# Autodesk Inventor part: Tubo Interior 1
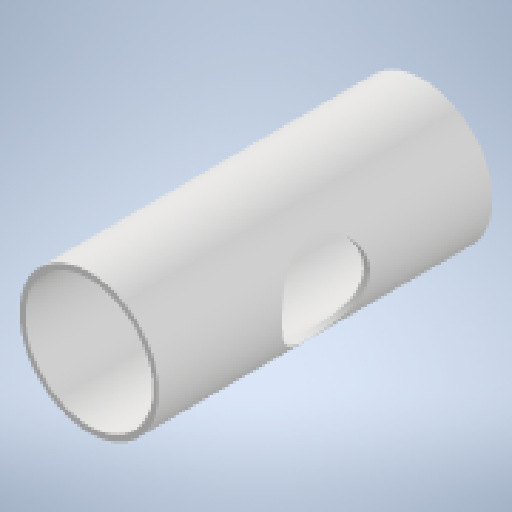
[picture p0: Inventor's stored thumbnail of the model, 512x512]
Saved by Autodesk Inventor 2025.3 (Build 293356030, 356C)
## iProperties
Created: 2025-10
Part Number: Tubo Interior 1
Material: Genérico
Document SubType Name: Modeling
Designer: Asus
Density: 1 g/cm^3
Appearance: Valor por defecto
Author: Asus
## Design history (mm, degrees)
sketch "Boceto1"
  geometry: C1 r 36.513 at (0, 0); C2 r 33.462 at (0, 0); 1 further point
  constraints: 2 centre point, 2 coincident
  dimensions: "d0" = 73.025 diameter of C1; "d1" = 3.05 radial gap between concentric circles of C1 C2
extrude "Extrusión1" new body sketch "Boceto1" stored distance "d2" = 175; taper "d3" = 0 deg
sketch "Boceto2"
  geometry: C1 r 23 at (0, 0); 1 further point
  constraints: 1 centre point, 1 coincident
  dimensions: "d4" = 46 diameter of C1
extrude "Extrusión2" cut sketch "Boceto2" extent not by distance; stored distance "d5" = 0; taper "d6" = 0 deg
node "Sólido1"
